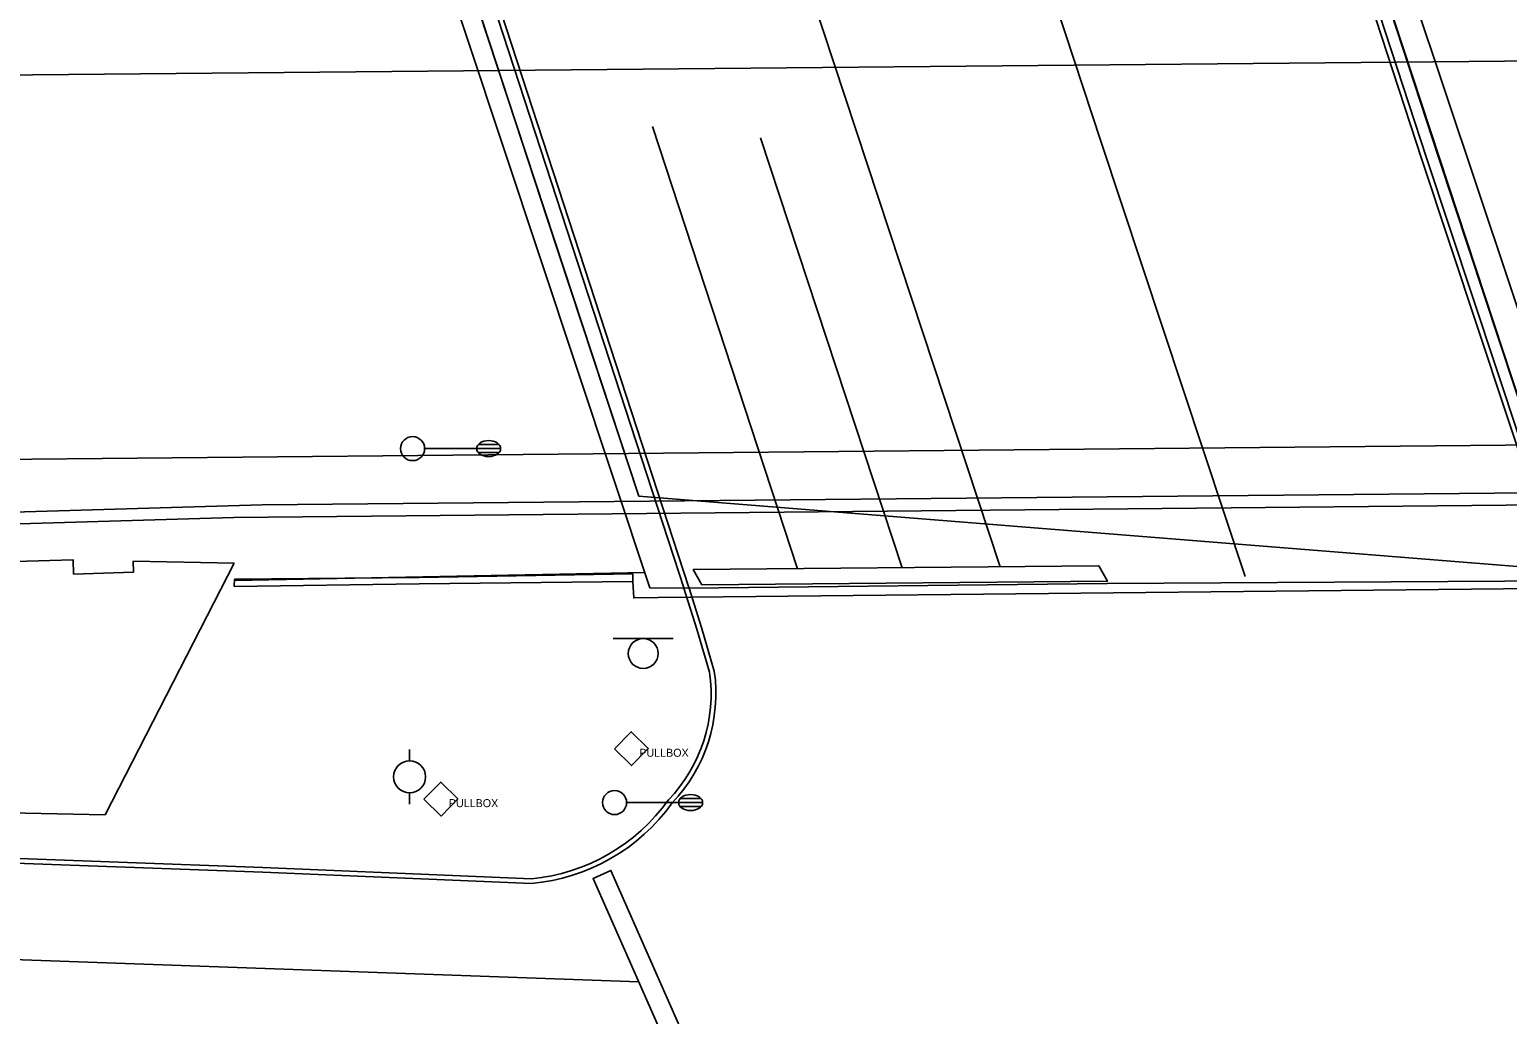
# Model space of a CAD drawing. Extents: x 2145380 to 2157287, y 139568 to 149130.
# Drawn here: x 2147239.5 to 2147424.2, y 142930.9 to 143054.1 of the extents above; entities that cross this region are included whole.
import ezdxf

# ---------------------------------------------------------------- set-up
doc = ezdxf.new("R2010")
doc.units = 0
for name, color, linetype in [('Default', 7, 'Continuous'), ('PR_PREVIOUSLY CONSTRUCTED', 7, 'Continuous'), ('TOPO_Bridge', 7, 'Continuous'), ('TOPO_BRIDGE_Floor Deck', 7, 'Continuous'), ('TOPO_BRIDGE_Low Beam', 7, 'Continuous'), ('TOPO_Curb Back', 7, 'Continuous'), ('TOPO_Light Pole', 7, 'Continuous'), ('TOPO_Misc Line', 7, 'Continuous'), ('TOPO_Power Pole', 7, 'Continuous'), ('TOPO_Power Pullbox', 7, 'Continuous'), ('TOPO_Sign', 7, 'Continuous'), ('TOPO_Wall Freestanding', 7, 'Continuous')]:
    doc.layers.add(name, color=color, linetype=linetype)

# ---------------------------------------------------------------- blocks, each defined once
blk = doc.blocks.new('LP')
at = {"layer": 'TOPO_Light Pole'}
blk.add_line((3.81, 0), (20.32, 0), dxfattribs=at)
for points in [[(20.32, 0), (27.94, 0)], [(20.32, 0), (23.5, 0)], [(20.83, 1.27), (27.43, 1.27)], [(20.83, 1.27), (23.5, 1.27)], [(23.71, 1.27), (27.43, 1.27)], [(23.71, 0), (27.94, 0)], [(20.83, -1.27), (27.43, -1.27)], [(20.83, -1.27), (23.5, -1.27)], [(23.71, -1.27), (27.43, -1.27)]]:
    blk.add_lwpolyline(points, dxfattribs=at)
blk.add_circle((0, 0), 3.81, dxfattribs=at)
blk.add_ellipse((24.13, 0), major_axis=(3.81, 0), ratio=0.666667, dxfattribs=at)
blk = doc.blocks.new('POWPOL')
at = {"layer": 'TOPO_Power Pole'}
for p, q in [((0, 10.16), (0, 17.34)), ((0, -10.16), (0, -17.34))]:
    blk.add_line(p, q, dxfattribs=at)
blk.add_circle((0, 0), 10.16, dxfattribs=at)
blk = doc.blocks.new('pulbox')
at = {"layer": 'Default'}
blk.add_lwpolyline([(-5.38, -0.01), (-0.02, 5.42), (5.4, 0.06), (0.05, -5.36), (-5.38, -0.01)], dxfattribs=at)
blk.add_text('PULLBOX', height=2.54, dxfattribs=at).set_placement((2.54, -2.54))

msp = doc.modelspace()

# ---------------------------------------------------------------- linework, layer by layer
at = {"layer": 'PR_PREVIOUSLY CONSTRUCTED'}
for p, q in [((2146054.19, 143037.14), (2147732.71, 143053.05)), ((2146653.08, 142994.81), (2148008.49, 143007.66)), ((2147265.03, 142993.04), (2147486.65, 142995.22))]:
    msp.add_line(p, q, dxfattribs=at)
for points in [[(2148008.6, 142995.66), (2147788.63, 142993.58), (2147488.58, 142996.73), (2147268.56, 142994.65), (2146968.63, 142985.8), (2146955.12, 142985.68), (2146653.19, 142982.81)], [(2147265.03, 142993.04), (2146968.66, 142984.3), (2146955.13, 142984.18), (2146653.2, 142981.31)]]:
    msp.add_lwpolyline(points, dxfattribs=at)
msp.add_lwpolyline([(2147265.08, 142987.34), (2147252.44, 142987.62), (2147252.48, 142986.22), (2147244.99, 142985.99), (2147244.94, 142987.78), (2147208.65, 142986.71), (2147208.93, 142956.72), (2147248.94, 142955.89)], close=True, dxfattribs=at)
at = {"layer": 'TOPO_Bridge'}
for points in [[(2147314.87, 142986), (2147314.86, 142985.07), (2147314.99, 142983.01), (2147318.06, 142983.07)], [(2147318.06, 142983.07), (2147435.89, 142984.28)]]:
    msp.add_lwpolyline(points, dxfattribs=at)
at = {"layer": 'TOPO_BRIDGE_Floor Deck'}
msp.add_lwpolyline([(2147436.61, 142985.9), (2147430.94, 142985.14), (2147374.14, 142984.81), (2147321.86, 142984.22), (2147317.02, 142984.28), (2147266.83, 143135.41), (2147272.28, 143136.04), (2147329.08, 143136.44), (2147381.28, 143136.94), (2147386.15, 143136.73), (2147400.2, 143094.81)], close=True, dxfattribs=at)
at = {"layer": 'TOPO_BRIDGE_Low Beam'}
for points in [[(2147315.63, 142995.71), (2147304.21, 143030.31), (2147281.68, 143099.17), (2147269.78, 143135.04)], [(2147432.69, 142986.37), (2147415.55, 143038.12), (2147399.9, 143086.04), (2147386.2, 143127.6)]]:
    msp.add_lwpolyline(points, dxfattribs=at)
for points in [[(2147269.78, 143135.04), (2147269.78, 143135.04), (2147281.68, 143099.17), (2147304.21, 143030.31), (2147315.63, 142995.71), (2147315.63, 142995.71)], [(2147386.2, 143127.6), (2147269.78, 143135.04), (2147281.68, 143099.17), (2147304.21, 143030.31), (2147315.63, 142995.71), (2147432.69, 142986.37), (2147415.55, 143038.12), (2147399.9, 143086.04)], [(2147269.78, 143135.04), (2147386.2, 143127.6), (2147432.69, 142986.37), (2147315.63, 142995.71)], [(2147386.2, 143127.6), (2147386.2, 143127.6), (2147399.9, 143086.04), (2147415.55, 143038.12), (2147432.69, 142986.37), (2147432.69, 142986.37)], [(2147315.63, 142995.71), (2147432.69, 142986.37), (2147432.69, 142986.37), (2147315.63, 142995.71)]]:
    msp.add_lwpolyline(points, close=True, dxfattribs=at)
at = {"layer": 'TOPO_Curb Back'}
for points in [[(2147381.13, 143136.84), (2147413.47, 143037.83), (2147430.98, 142985.09)], [(2147381.7, 143137.03), (2147414.04, 143038.02), (2147431.55, 142985.28)], [(2147321.3, 142984.13), (2147290.03, 143080.04), (2147271.05, 143135.84)], [(2147321.87, 142984.32), (2147290.6, 143080.23), (2147271.62, 143136.03)], [(2147321.27, 142984.23), (2147322.89, 142979.12), (2147324.47, 142973.71)], [(2147321.9, 142984.22), (2147323.46, 142979.29), (2147325.06, 142973.84)], [(2147302.2, 142947.89), (2147268.65, 142949.31), (2147196.44, 142951.96), (2147104.86, 142955.1), (2147007.45, 142958.52), (2146919.46, 142961.11), (2146829.72, 142964.19), (2146749.05, 142964.32), (2146671.05, 142963.99)], [(2147302.21, 142947.29), (2147268.63, 142948.71), (2147196.42, 142951.36), (2147104.83, 142954.5), (2147007.43, 142957.92), (2146919.44, 142960.51), (2146829.71, 142963.59), (2146749.05, 142963.72), (2146671.37, 142963.39)]]:
    msp.add_lwpolyline(points, dxfattribs=at)
for centre, radius, start, end in [((2147305.4, 142971.05), 19.26, 316.3511, 7.9529), ((2147305.4, 142971.05), 19.86, 316.4749, 8.0807), ((2147300.01, 142971.53), 23.73, 275.2939, 324.5229), ((2147300.01, 142971.53), 24.33, 275.1982, 324.4222)]:
    msp.add_arc(centre, radius, start, end, dxfattribs=at)
at = {"layer": 'TOPO_Misc Line'}
for p, q in [((2147335.45, 142986.66), (2147317.34, 143041.92)), ((2147348.53, 142986.78), (2147330.85, 143040.51)), ((2147236.27, 142937.85), (2147315.62, 142935.01))]:
    msp.add_line(p, q, dxfattribs=at)
for points in [[(2147360.77, 142986.89), (2147326.16, 143091.87), (2147312.04, 143135.08)], [(2147342.08, 143134.35), (2147354.39, 143097.74), (2147373.37, 143040.11), (2147391.38, 142985.67)]]:
    msp.add_lwpolyline(points, dxfattribs=at)
for points in [[(2147323.52, 142984.63), (2147322.44, 142986.55), (2147373.12, 142987), (2147374.19, 142985.09)], [(2147325.53, 142912.53), (2147309.91, 142947.95), (2147312.15, 142948.94), (2147327.77, 142913.52)]]:
    msp.add_lwpolyline(points, close=True, dxfattribs=at)
at = {"layer": 'TOPO_Sign'}
for points in [[(2147312.43, 142977.93), (2147319.92, 142977.93)], [(2147316.18, 142977.93), (2147316.18, 142977.93)], [(2147314.31, 142976.06), (2147314.31, 142976.06)], [(2147318.05, 142976.06), (2147318.05, 142976.06)], [(2147316.18, 142974.19), (2147316.18, 142974.19)]]:
    msp.add_lwpolyline(points, dxfattribs=at)
for start, end in [(90, 180), (360, 90), (180, 270), (270, 0)]:
    msp.add_arc((2147316.18, 142976.06), 1.87, start, end, dxfattribs=at)
at = {"layer": 'TOPO_Wall Freestanding'}
msp.add_line((2147316.38, 142986.2), (2147265.15, 142985.2), dxfattribs=at)
for points in [[(2147265.11, 142985.34), (2147265.07, 142984.44), (2147288.17, 142984.78), (2147314.86, 142985.07)], [(2147265.11, 142985.34), (2147288.19, 142985.56), (2147314.87, 142986)]]:
    msp.add_lwpolyline(points, dxfattribs=at)

# ---------------------------------------------------------------- block references
at = {"layer": 'TOPO_Light Pole', "xscale": 0.39370000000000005, "yscale": 0.3937000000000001}
for p in [(2147287.36, 143001.67), (2147312.6, 142957.42)]:
    msp.add_blockref('LP', p, dxfattribs=at)
at = {"layer": 'TOPO_Power Pole', "xscale": 0.19685000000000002, "yscale": 0.19685000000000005}
msp.add_blockref('POWPOL', (2147286.99, 142960.64), dxfattribs=at)
at = {"layer": 'TOPO_Power Pullbox', "xscale": 0.39370000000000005, "yscale": 0.3937000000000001}
for p in [(2147314.69, 142964.15), (2147290.89, 142957.85)]:
    msp.add_blockref('pulbox', p, dxfattribs=at)

doc.saveas('drawing.dxf')
